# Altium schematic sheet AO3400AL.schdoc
size 127 x 101 mm
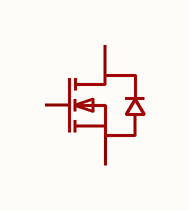
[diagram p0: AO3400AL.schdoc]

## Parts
Q?  ao3400al  [SOT-23-3_L2.9-W1.3-P1.90-LS2.4-BR]  (value not drawn)

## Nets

Not connected (* = marked no-connect by the designer): Q? 1(G) 2(S) 3(D)

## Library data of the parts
Q? = ao3400al: 漏源电压(Vdss):30V;连续漏极电流(Id):5.8A;导通电阻(RDS(on)):22mΩ@10V;耗散功率(Pd):1.25W;阈值电压(Vgs(th)):1.1V;; Manufacturer: TECH PUBLIC(台舟); AddInBom: yes; ModelId: c62791f0466c4ae2a892c056b845b0ca; ModelName: SOT-23-3P_L2.9-W1.3-H1.0-LS2.4-P0.95; ModelTransform: 98.425,114.173,0,180,0,0,0.0005,-0.0005,0; Drain to Source Voltage: 30V; Current - Continuous Drain(Id): 5.8A; Pd - Power Dissipation: 1.25W; Gate Threshold Voltage (Vgs(th)): 1.1V; Gate Charge(Qg): 9nC@4.5V; Input Capacitance(Ciss): 550pF; Reverse Transfer Capacitance (Crss@Vds): 57pF; Output Capacitance(Coss): 72pF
